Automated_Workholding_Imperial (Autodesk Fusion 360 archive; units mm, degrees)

design "Automated_Workholding_Start_Imperial" references "Broached Hexagon Socket Head Cap Screw ANSI B18.3.1M - M12x1.75 x 60 Steel Grade 2 Plain", "autodesk 5ax table ac head xyz"
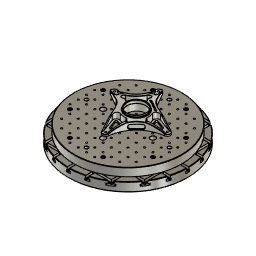
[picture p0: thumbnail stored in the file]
part number: Configuration 1
description: Part Number
part number: Hub
part number: Hub Stock
parameter "d185" = 0
base_feature "Base Feature1" bodies "c_axis_table"
sketch "Sketch1" plane through (0, 0, -15.5) normal (0, 0, -1) x axis (1, 0, 0)
  line L1 (93, 7) -> (59.5903, 7)
  line L2 (93, 93) -> (93, 7)
  line L3 (7, 93) -> (93, 93)
  line L4 (7, 59.5903) -> (7, 93)
  line L5 (12, 88) -> (12, 58.7878)
  line L6 (88, 88) -> (12, 88)
  line L7 (88, 12) -> (88, 88)
  line L8 (58.7878, 12) -> (88, 12)
  line L9 (293, -93) -> (293, -107)
  line L10 (256.1738, -100) -> (293, -100)
  arc A1 centre (0, 0) radius 60 clockwise from (58.7878, 12) to (59.5903, 7)
  arc A2 centre (0, 0) radius 60 clockwise from (7, 59.5903) to (12, 58.7878)
  circle C1 centre (0, 0) radius 275
  point P14 (293, -107)
  point P16 (293, -107)
  point P15 (293, -93)
  point P17 (293, -93)
  point P18 (293, -100)
  point P19 (256.1738, -100)
  point P20 (256.1738, -100)
  concentric A1 C1
  coincident P14 P16
  coincident P15 P17
  midpoint L9 P18
  coincident C1 P19
  perpendicular L9 L10
  coincident P19 P20
  dimension "d1" diameter C1 = 550
  dimension "d181" alignAngle = 0
  dimension "d182" alignOffsetX = 0
  dimension "d183" alignOffsetY = 0
  dimension "d184" alignOffsetZ = 0
  dimension "d185" alignAngle = 0
  dimension "d186" alignOffsetX = 0
  dimension "d187" alignOffsetY = 0
  dimension "d188" alignOffsetZ = 0
  dimension "d189" alignAngle = 0
  dimension "d190" alignOffsetX = 0
  dimension "d191" alignOffsetY = 0
  dimension "d192" alignOffsetZ = 0
  dimension "d193" alignAngle = 0
  dimension "d194" alignOffsetX = 0
  dimension "d195" alignOffsetY = 0
  dimension "d196" alignOffsetZ = 0
  dimension "d197" alignAngle = 0
  dimension "d198" alignOffsetX = 0
  dimension "d199" alignOffsetY = 0
  dimension "d200" alignOffsetZ = 0
  dimension "d201" alignAngle = 0
  dimension "d202" alignOffsetX = 0
  dimension "d203" alignOffsetY = 0
  dimension "d204" alignOffsetZ = 0
  dimension "d205" alignAngle = 0
  dimension "d206" alignOffsetX = 0
  dimension "d207" alignOffsetY = 0
  dimension "d208" alignOffsetZ = 0
  dimension "d209" alignAngle = 0
  dimension "d210" alignOffsetX = 0
  dimension "d211" alignOffsetY = 0
  dimension "d212" alignOffsetZ = 0
as_built_joint "As-built1"
work_plane "WorkPlane1"
sketch "Sketch1" plane through (256.1738, 100, -15.5) normal (-1, 0, 0) x axis (0, -1, 0)
  line L1 (0, 5) -> (0, -9)
  line L2 (7, 5) -> (0, 5)
  line L3 (11, -9) -> (0, -9)
  line L4 (11, 0) -> (11, -9)
  line L5 (7, 0) -> (11, 0)
  line L6 (7, 5) -> (7, 0)
  line L7 (-7, 5) -> (0, 5)
  line L8 (-7, 5) -> (-7, 0)
  line L9 (-7, 0) -> (-11, 0)
  line L10 (-11, 0) -> (-11, -9)
  line L11 (-11, -9) -> (0, -9)
  point P5 (0, 0)
  point P9 (7, 0)
  point P2 (0, -9)
  point P15 (0, -9)
  point P3 (0, 5)
  point P10 (0, 5)
  point P4 (7, 5)
  point P11 (-7, 5)
  point P6 (11, -9)
  point P14 (-11, -9)
  point P7 (11, 0)
  point P13 (-11, 0)
  point P8 (7, 0)
  point P12 (-7, 0)
  vertical L1
  perpendicular L1 L2
  coincident L1 P5
  perpendicular L1 L3
  perpendicular L3 L4
  perpendicular L1 L5
  perpendicular L2 L6
  coincident L5 P9
  symmetric P2 L1 P15
  symmetric P3 L1 P10
  symmetric L1 P4 P11
  symmetric L1 P6 P14
  symmetric L1 P7 P13
  symmetric L1 P8 P12
  dimension "d4" distance L1 P4 = 7 (= "( 14 / 2 ) * 1 mm")
  dimension "d5" distance P2 P3 = 14
  dimension "d6" distance P2 P6 = 11 (= "( 22 / 2 ) * 1 mm")
  dimension "d7" distance P6 P7 = 9
extrude "Extrude1" new body sketch "Sketch1" profile of L2 L3 L4 L5 L6 L7 L8 L9 L10 L11 distance 29
hole "Hole1" HoleDiameter 10.274 TipAngle 118
chamfer "Chamfer1" distance 3 distance 1
as_built_joint "As-built1"
mirror_component "MirrorComponent1"
derived_instance "DerivedInstance1"
as_built_joint "As-built2"
step "00000000-0000-0000-0000-000000000000" TotalAngle 360
work_plane "WorkPlane1" AlongDistance 20
sketch "Sketch1" plane through (0, 0, 20) normal (0, 0, 1) x axis (1, 0, 0)
  line L1 (0, 66.3083) -> (0, 0)
  circle C1 centre (100, -256.1738) radius 5.1368
  circle C2 centre (256.1738, -100) radius 5.1368
  circle C3 centre (256.1738, 100) radius 5.1368
  circle C4 centre (100, 256.1738) radius 5.1368
  circle C5 centre (-100, 256.1738) radius 5.1368
  circle C6 centre (-256.1738, 100) radius 5.1368
  circle C7 centre (-256.1738, -100) radius 5.1368
  circle C8 centre (-100, -256.1738) radius 5.1368
  point P1 (0, 0)
  point P3 (0, 0)
  coincident P1 P3
  vertical L1
sketch "Sketch1" plane through (0, 0, 0) normal (0, 0, 1) x axis (-1, 0, 0)
  line L1 (-7, 193) -> (-7, 107)
  line L2 (-93, 193) -> (-7, 193)
  line L3 (-93, 107) -> (-93, 193)
  line L4 (-7, 107) -> (-93, 107)
  circle C1 centre (0, 0) radius 325
  point P1 (0, 0)
  point P6 (0, 0)
  coincident P1 P6
  dimension "d91" diameter C1 = 650
extrude "Extrude1" new body sketch "Sketch1" along normal blind 50
sketch "Sketch2" plane through (0, 0, 50) normal (0, 0, 1) x axis (-1, 0, 0)
  line L1 (7, -207) -> (7, -293)
  line L2 (-7, -293) -> (-7, -207)
  line L3 (-7, -250) -> (7, -250)
  line L4 (-25, -25) -> (25, -25)
  line L5 (-25, 25) -> (-25, -25)
  line L6 (25, 25) -> (-25, 25)
  line L7 (25, -25) -> (25, 25)
  line L8 (-25, 25) -> (25, -25)
  line L9 (25, 25) -> (-25, -25)
  circle C1 centre (0, 0) radius 325
  point P7 (7, -250)
  point P8 (-7, -250)
  point P9 (0, -250)
  point P14 (0, 0)
  point P2 (0, 0)
  point P12 (-25, 25)
  point P13 (25, 25)
  point P11 (-25, -25)
  midpoint L1 P7
  midpoint L2 P8
  midpoint L3 P9
  horizontal L4
  perpendicular L4 L5
  parallel L4 L6
  parallel L5 L7
  coincident L8 P14
  coincident L9 P14
  coincident P2 P14
  dimension "d152" distance P12 P13 = 50
  dimension "d153" distance P11 P12 = 50
hole "Hole1" HoleDiameter 13 TipAngle 118 CBDepth 12 CBDiameter 20
rectangular_pattern "R-Pattern1" uSpaceDistance 100 vSpaceDistance 0
circular_pattern "C-Pattern1" TotalAngle 360
as_built_joint "As-built2"
step "Screw1"
joint "Assemble1" alignAngle 0 alignOffsetX 0 alignOffsetY 0 alignOffsetZ 0
step "Screw2"
joint "Assemble2" alignAngle 0 alignOffsetX 0 alignOffsetY 0 alignOffsetZ 0
step "Screw4"
joint "Assemble4" alignAngle 0 alignOffsetX 0 alignOffsetY 0 alignOffsetZ 0
step "Screw6"
joint "Assemble6" alignAngle 0 alignOffsetX 0 alignOffsetY 0 alignOffsetZ 0
step "Screw7"
joint "Assemble7" alignAngle 0 alignOffsetX 0 alignOffsetY 0 alignOffsetZ 0
step "Screw9"
joint "Assemble9" alignAngle 0 alignOffsetX 0 alignOffsetY 0 alignOffsetZ 0
step "Screw10"
joint "Assemble10" alignAngle 0 alignOffsetX 0 alignOffsetY 0 alignOffsetZ 0
step "Screw12"
joint "Assemble12" alignAngle 0 alignOffsetX 0 alignOffsetY 0 alignOffsetZ 0
hole "Hole2" HoleDepth 106.5 HoleDiameter 10.274 TipAngle 118
rectangular_pattern "R-Pattern2" countU 12 CountV 12 uSpaceDistance 50 vSpaceDistance 50
hole "Hole3" HoleDiameter 30 TipAngle 180
rectangular_pattern "R-Pattern3" uSpaceDistance 150 vSpaceDistance 150
chamfer "Chamfer1" distance 1 distance 2
base_feature "Base Feature1" bodies "Model"
position "Position2"
joint "Assemble21" alignAngle 45 named "Angle" alignOffsetX 76.2 named "X_Offset" alignOffsetY 50.8 named "Y_Offset" alignOffsetZ 0 named "Height"
base_feature "Base Feature1"
joint "Assemble22" alignAngle 0 alignOffsetX 0 alignOffsetY 0 alignOffsetZ 0
copy_paste_bodies "CutPasteBodies"
remove_instance "RemoveInstance1"
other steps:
derived_base_feature "Derived Base Feature"
thread "Thread1" ThreadOffset 0 ThreadDepth 7.4
base_feature "Base Feature3" bodies "Stock"
thread "Thread1" ThreadOffset 0 ThreadDepth 7.4
create_component "CreateComponent1"
create_component "CreateComponent1"
create_component "CreateComponent2"
create_component "CreateComponent2"
joint_origin "JointOrigin1"
joint_origin "JointOrigin2"
joint_origin "JointOrigin4"
joint_origin "JointOrigin6"
joint_origin "JointOrigin7"
joint_origin "JointOrigin9"
joint_origin "JointOrigin10"
joint_origin "JointOrigin12"
create_component "CreateComponent4"
create_component "CreateComponent5"
joint_origin "JointOrigin1"
joint_origin "JointOrigin13"
joint_origin "JointOrigin2"
create_component "CreateComponent7"
remove_body "RemoveBody1"
named bodies: "c_axis_table", "Model", "Stock"

design "Broached Hexagon Socket Head Cap Screw ANSI B18.3.1M - M12x1.75 x 60 Steel Grade 2 Plain"
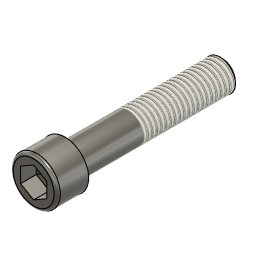
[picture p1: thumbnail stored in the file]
description: Broached Hexagon Socket Head Cap Screw ANSI B18.3.1M - M12x1.75 x 60
part number: arrangementsContainer
parameter "adsk_nomlen" = 60
parameter "adsk_headh" = 12
parameter "adsk_headdia" = 18
parameter "adsk_nomdia" = 12
parameter "adsk_philwidth" = 10
parameter "adsk_phildepth" = 6
parameter "adsk_thrlen" = 36
parameter "adsk_startlen" = 1.0735
parameter "adsk_endpointdia" = 9.8529
sketch "Sketch1" plane through (0, 0, 0) normal (0, 1, 0) x axis (1, 0, 0)
  line L1 (-6, 60) -> (-6, 0)
  line L2 (0, 60) -> (-6, 60)
  line L3 (0, -12) -> (0, 60)
  line L4 (-9, 0) -> (-6, 0)
  line L5 (-9, -12) -> (-9, 0)
  line L6 (0, -12) -> (-9, -12)
  point P1 (0, 0)
  point P4 (0, 60)
  point P7 (0, -12)
  point P5 (-9, 0)
  point P6 (-9, -12)
  perpendicular L1 L2
  collinear P1 P4 P7
  perpendicular L1 L4
  coincident P1 L4
  vertical L1
  vertical L3
  parallel L3 L5
  coincident L3 P7
  perpendicular L3 L6
  dimension "d9" = 12 (= "adsk_nomdia")
  dimension "d66" = 18 (= "adsk_headdia")
  dimension "d68" distance P1 P4 = 60 (= "adsk_nomlen")
  dimension "d79" distance P5 P6 = 12 (= "adsk_headh")
revolve "Revolve1" sketch "Sketch1" AlongAngle 360
work_plane "WorkPlane1" AlongDistance 12 (= "adsk_headh")
sketch "Sketch6" plane through (0, 0, 12) normal (0, 0, 1) x axis (1, 0, 0)
  line L1 (5, 0) -> (-5, 0)
  line L2 (-5, 2.8868) -> (0, 0)
  line L3 (-5, 2.8868) -> (-5, -2.8868)
  line L4 (0, 0) -> (-5, -2.8868)
  point P1 (0, 0)
  point P4 (0, 0)
  point P2 (-5, 0)
  point P5 (-5, 2.8868)
  point P7 (-5, 2.8868)
  point P8 (0, 0)
  point P3 (5, 0)
  horizontal L1
  midpoint P1 L1
  coincident P1 P4
  perpendicular L1 L3
  midpoint P2 L3
  coincident P5 P7
  coincident P1 P8
  dimension "d72" distance P2 P3 = 10 (= "adsk_philwidth")
  dimension "d100" angle L1 L2 = 150
extrude "Extrude1" cut sketch "Sketch6" profile of L2 L3 L4 no distance stored
circular_pattern "C-Pattern1" TotalAngle 360
extrude "Extrude2" cut of existing geometry no distance stored taper -85
thread "Thread2" ThreadOffset 0 ThreadLength 36 (= "adsk_thrlen")
fillet "Fillet4" radius 1.2 (= "adsk_nomdia * 0.1")
sketch "Sketch7" plane through (0, 0, 0) normal (0, 1, 0) x axis (1, 0, 0)
  line L1 (-6.12, 58.9265) -> (-6.12, 60)
  line L2 (-4.9265, 60) -> (-6.12, 58.9265)
  line L3 (0, -12) -> (0, 60)
  line L4 (0, 60) -> (-6.12, 60)
  point P5 (0, 60)
  point P7 (0, 60)
  point P4 (-4.9265, 60)
  point P3 (-6.12, 58.9265)
  point P1 (0, 0)
  coincident P5 P7
  perpendicular L3 L4
  coincident P4 L4
  perpendicular L1 L4
  dimension "d92" distance P3 P4 = 1.0735 (= "adsk_startlen")
  dimension "d98" distance P1 P4 = 4.9265 (= "adsk_endpointdia / 2")
  dimension "d99" distance P1 L1 = 6.12 (= "adsk_nomdia * 0.51")
revolve "Revolve3" sketch "Sketch7" AlongAngle 360
joint_origin "JointOrigin2" OffsetX 0 OffsetY 0 OffsetZ 0 AngleZ 0

design "autodesk 5ax table ac head xyz"
named bodies: "base", "a_axis_table", "c_axis_table", "y_axis_head", "x_axis_head", "z_axis_cover", "z_axis_head"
